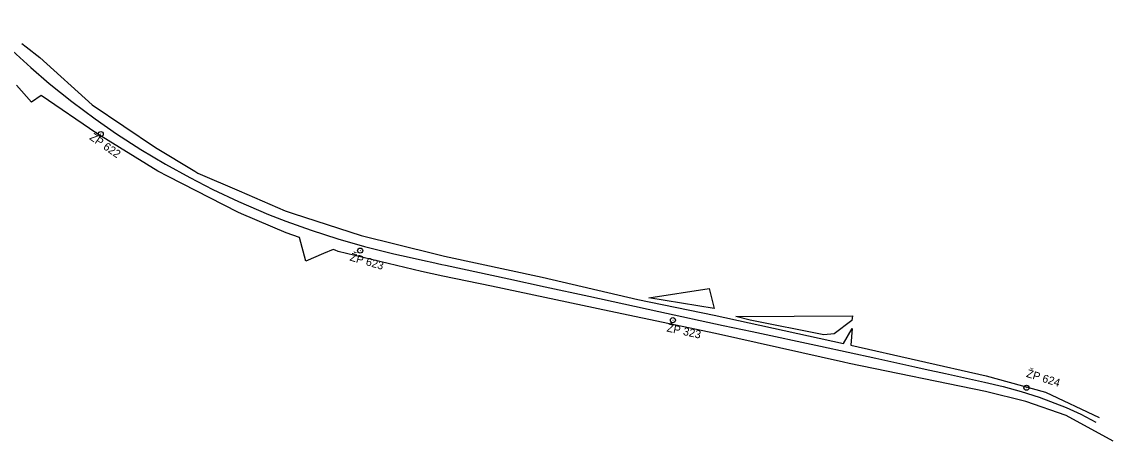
# Model space of a CAD drawing. Extents: x -792643 to -787072, y -1118436 to -1109677.
# Drawn here: x -789315 to -788660, y -1114725 to -1114474 of the extents above; entities that cross this region are included whole.
import ezdxf

# ---------------------------------------------------------------- set-up
doc = ezdxf.new("R2010")
doc.units = 0
for name, color, linetype in [('Vrstva 1', 7, 'Continuous'), ('Vrstva 53', 7, 'Continuous'), ('Vrstva 63', 7, 'Continuous')]:
    doc.layers.add(name, color=color, linetype=linetype)

msp = doc.modelspace()

# ---------------------------------------------------------------- linework, layer by layer
at = {"layer": 'Vrstva 1'}
for points in [[(-789338.53, -1114473.65), (-789330.19, -1114481.81), (-789322.58, -1114489.09), (-789309.34, -1114501.13), (-789298.32, -1114510.55), (-789284.69, -1114521.46), (-789270.77, -1114531.83), (-789257.88, -1114540.78), (-789243.27, -1114550.25), (-789228.51, -1114559.09), (-789214.02, -1114567.11), (-789200.11, -1114574.26), (-789184.73, -1114581.5), (-789166.72, -1114589.18), (-789156.33, -1114593.21), (-789141.12, -1114598.67), (-789125.25, -1114603.78), (-789109.13, -1114608.43), (-789091.69, -1114612.82), (-789082.49, -1114614.9), (-789072.68, -1114617.04)], [(-789072.68, -1114617.04), (-789068.77, -1114617.89), (-789062.83, -1114619.18), (-789060.63, -1114619.65), (-789022.6, -1114627.9), (-789000.74, -1114632.63), (-788974.55, -1114638.3), (-788932.61, -1114647.36), (-788894.07, -1114655.7), (-788876.7, -1114659.44), (-788835.62, -1114668.28), (-788802.42, -1114675.49), (-788779.02, -1114680.58), (-788772.92, -1114681.91), (-788760.72, -1114684.57)], [(-788760.72, -1114684.57), (-788748.04, -1114687.36), (-788737.27, -1114689.76), (-788726.1, -1114692.42), (-788715.23, -1114695.34), (-788704.4, -1114698.71), (-788688.33, -1114704.93), (-788679.49, -1114709.06), (-788670.47, -1114713.83)]]:
    msp.add_lwpolyline(points, dxfattribs=at)
at = {"layer": 'Vrstva 53'}
for points in [[(-789314.65, -1114486.55), (-789312.07, -1114488.61), (-789303.95, -1114495.11), (-789272.62, -1114523.48), (-789234.48, -1114549.02), (-789211.01, -1114563.21), (-789209.16, -1114564.33), (-789184.43, -1114575.03), (-789156.73, -1114587.01), (-789151.91, -1114588.58), (-789111.21, -1114601.86), (-789066.78, -1114612.81), (-789061.16, -1114614.19), (-789002.52, -1114626.82), (-788945.18, -1114640.28), (-788899.34, -1114649.59)], [(-788660.09, -1114725.18), (-788688.38, -1114709.77), (-788712.4, -1114701.34), (-788736.68, -1114695.45), (-788818.39, -1114678.6), (-788821.94, -1114677.87), (-788898.55, -1114660.57), (-788962.34, -1114647.14), (-789033.04, -1114632.27), (-789062.17, -1114626.14), (-789068.5, -1114624.81), (-789075.07, -1114623.43), (-789124.89, -1114611.37), (-789126.69, -1114610.58), (-789127.89, -1114610.16), (-789133.75, -1114612.63), (-789144.37, -1114617.13), (-789148.2, -1114602.99), (-789156.19, -1114600.12), (-789182.88, -1114588.76), (-789185.19, -1114587.78), (-789226.93, -1114566.34), (-789233.09, -1114563.18), (-789269.72, -1114540.6), (-789303.08, -1114517.85), (-789308.97, -1114521.75), (-789318.04, -1114511.65)], [(-788899.34, -1114649.59), (-788821.82, -1114666.61), (-788816.69, -1114657.55), (-788817.52, -1114667.59)], [(-788817.52, -1114667.59), (-788736.3, -1114686.03), (-788700.64, -1114695.78), (-788668.56, -1114710.95)]]:
    msp.add_lwpolyline(points, dxfattribs=at)
for points in [[(-788938.55, -1114639.25), (-788902.51, -1114633.65), (-788899.53, -1114645.51)], [(-788886.49, -1114650.35), (-788816.4, -1114650.04), (-788816.78, -1114652.84), (-788827.38, -1114660.85), (-788833.62, -1114661.44), (-788877.76, -1114652.59)]]:
    msp.add_lwpolyline(points, close=True, dxfattribs=at)
at = {"layer": 'Vrstva 63'}
for p, q in [((-789267.47, -1114540.91), (-789267.3, -1114541.02)), ((-789111.87, -1114610.87), (-789111.68, -1114610.92)), ((-788924.28, -1114652.58), (-788924.09, -1114652.62)), ((-788712.21, -1114693.08), (-788712.02, -1114693.14))]:
    msp.add_line(p, q, dxfattribs=at)
for centre in [(-789267.39, -1114540.97), (-789111.78, -1114610.9), (-788924.18, -1114652.6), (-788712.12, -1114693.11)]:
    msp.add_circle(centre, 1.51, dxfattribs=at)

# ---------------------------------------------------------------- texts
for s, rotation, p in [('ŽP 622', 325.23583, (-789274.57, -1114543.86)), ('ŽP 623', 343.92559, (-789118.37, -1114616.75)), ('ŽP 323', 347.78356, (-788928.16, -1114659.34)), ('ŽP 624', 342.6975, (-788712.55, -1114686.54))]:
    msp.add_text(s, height=4.8, rotation=rotation, dxfattribs=at).set_placement(p)

doc.saveas('drawing.dxf')
